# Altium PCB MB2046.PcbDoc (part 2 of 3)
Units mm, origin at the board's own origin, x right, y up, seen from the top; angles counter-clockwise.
Board outline 70 x 82.5 mm, 2 copper layers (Top Layer, Bottom Layer), stack 1.47 mm thick; 179 components, 148 nets, 719 pads, 862 vias.
Unrouted connection lines stored in the file: 135.
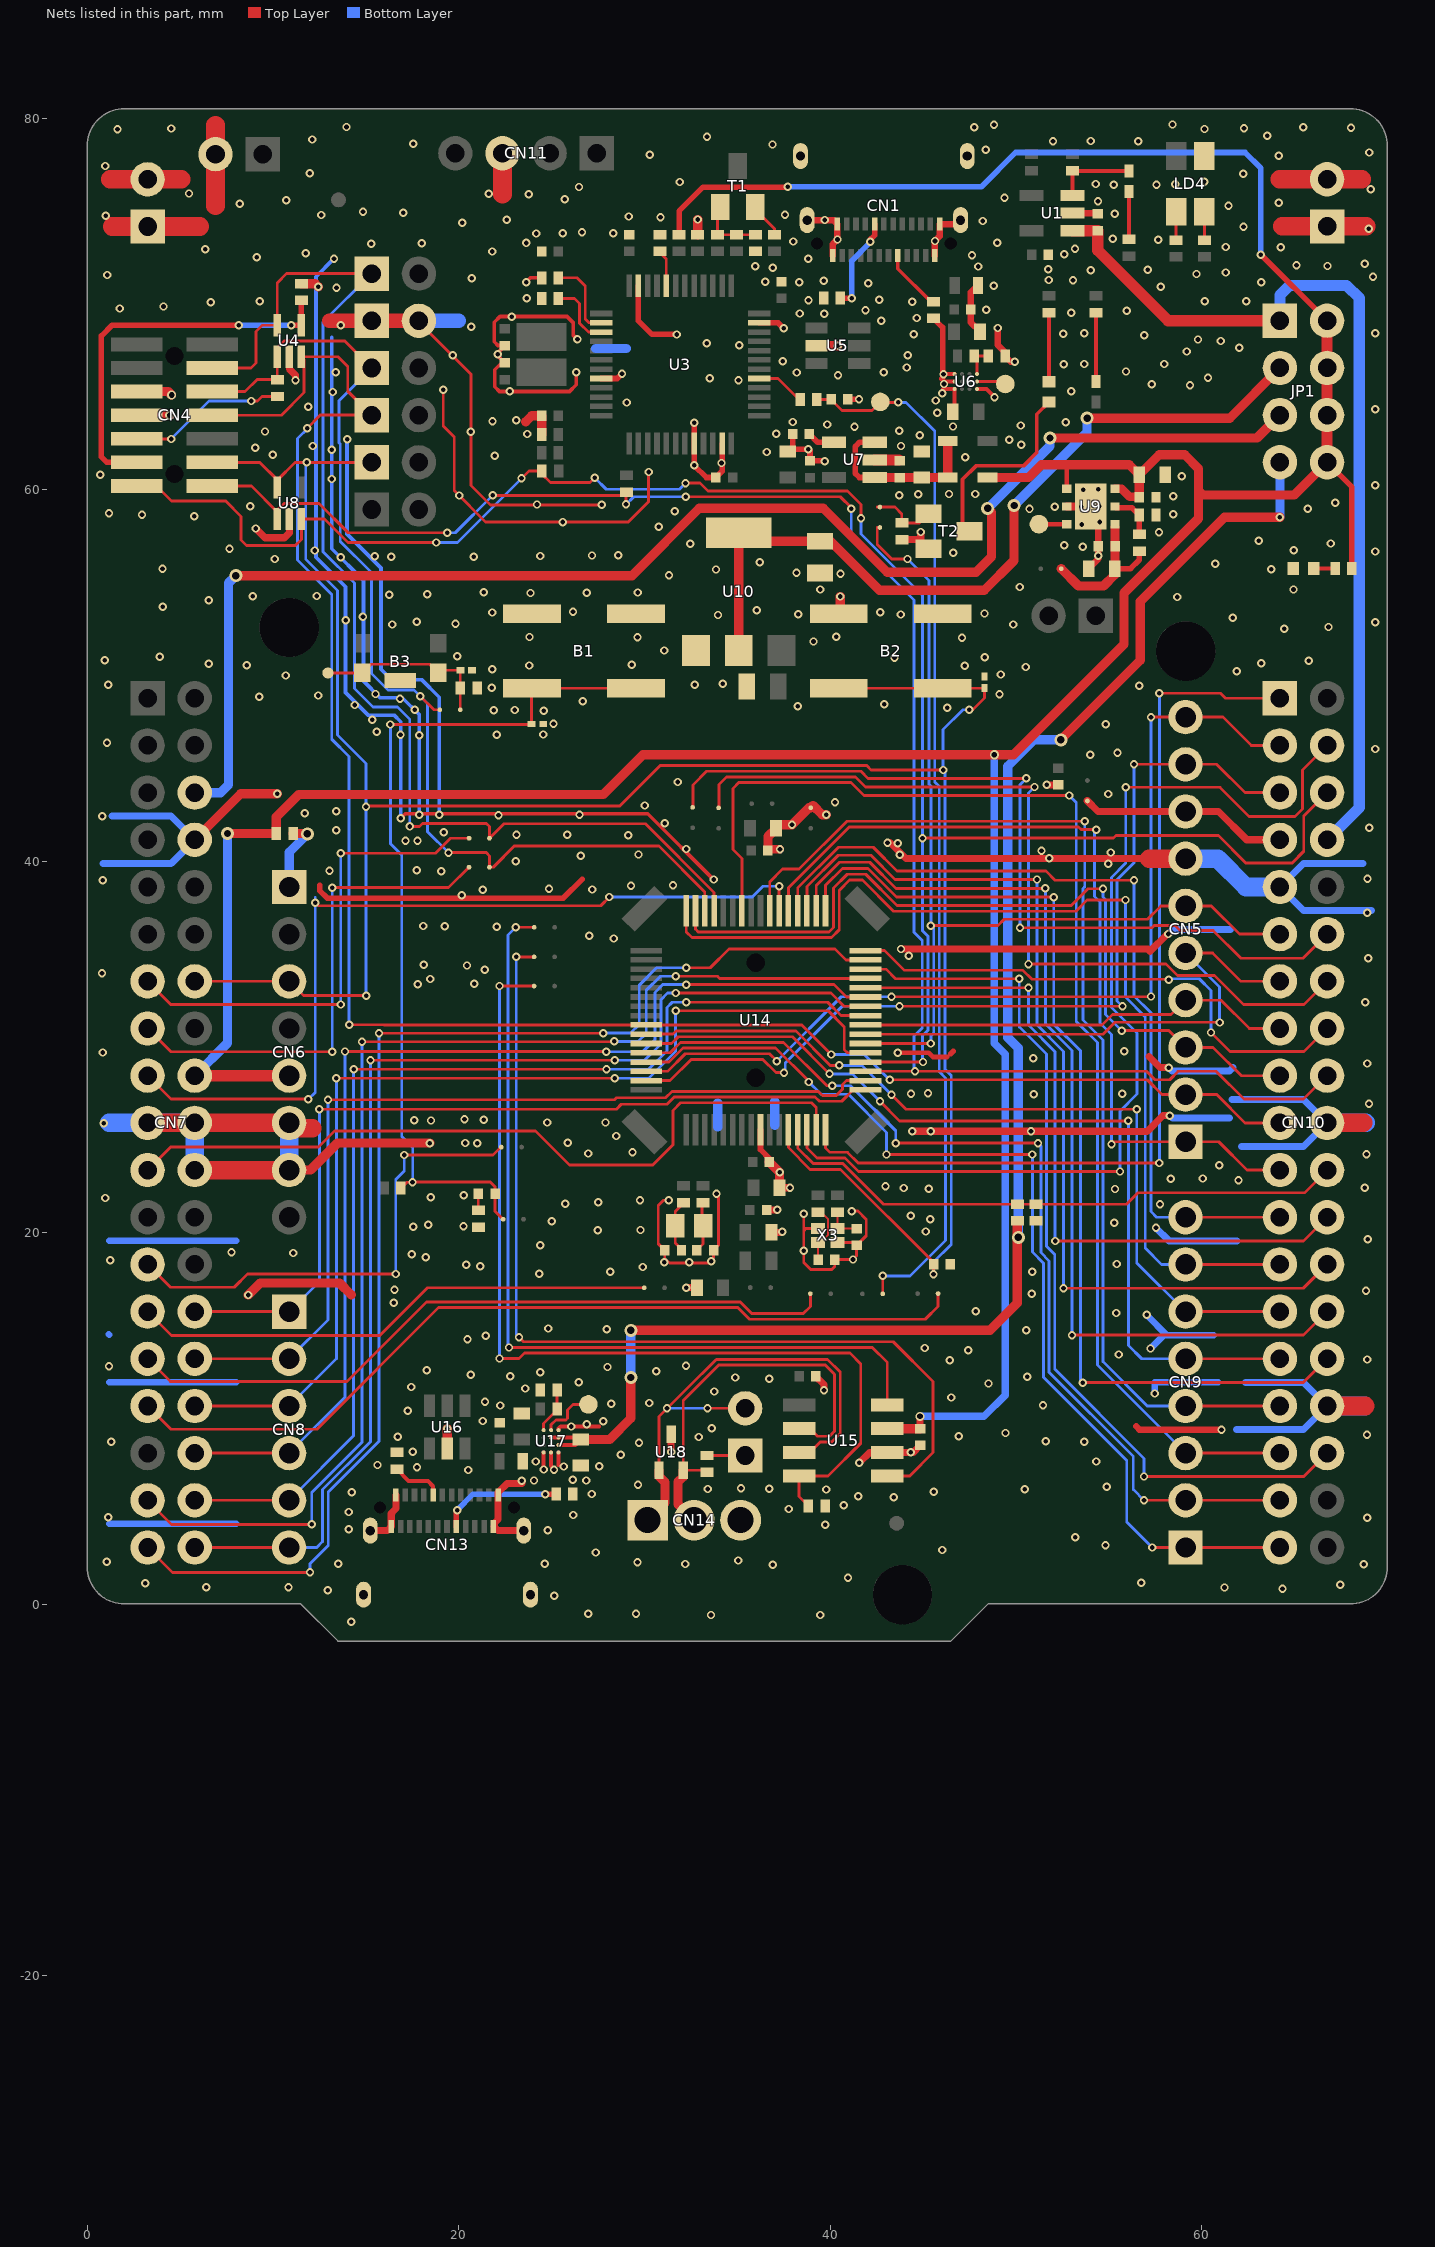
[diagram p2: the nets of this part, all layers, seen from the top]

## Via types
v1: diameter 0.45, hole 0.25, Top Layer to Bottom Layer, tented both sides, 830 vias
v2: diameter 0.7, hole 0.4, Top Layer to Bottom Layer, tented both sides, 21 vias
v3: diameter 0.5, hole 0.3, Top Layer to Bottom Layer, tented both sides, 11 vias

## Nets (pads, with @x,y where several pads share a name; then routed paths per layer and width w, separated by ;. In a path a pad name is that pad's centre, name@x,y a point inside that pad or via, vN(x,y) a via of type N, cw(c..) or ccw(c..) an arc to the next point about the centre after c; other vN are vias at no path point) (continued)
5V: C18.2 C20.2 C41.1 CN6.5 CN7.18 D2.1 JP1.2 JP1.4 JP1.6 JP1.8 R9.2 R31.1 R33.1 U9.1 U9.6 U15.3 | length 208.4
  Top Layer w0.25: U9.1@52.736,60.04 52.736,61.333
  Top Layer w0.3: R9.2@31.863,73.72 31.863,74.993 33.158,76.288 37.7,76.288 v1(37.71,76.298) ; v1(63.18,72.635) 63.18,72.663 JP1.2@66.75,69.093 JP1.2@66.75,69.842 ; JP1.8@66.75,61.473 68.083,60.14 R31.1@68.083,55.753
  Top Layer w0.4: C41.1@44.835,9.45 v3(44.835,10.105)
  Top Layer w0.45: U9.6@55.336,60.04 55.695,60.04 56.118,59.617 56.391,59.617 56.416,59.592 C20.2@56.64,59.592
  Top Layer w0.5: v2(7.552,41.485) R33.1@10.182,41.485 10.182,42.38 11.385,43.583 27.785,43.583 29.923,45.72 49.865,45.72 55.812,51.667 55.812,54.432 59.828,58.448 59.828,59.935 ; U15.3@43.076,9.442 C41.1@44.843,9.442 ; D2.1@48.465,60.65 50.688,60.65 51.38,61.343 56.092,61.343 C18.2@56.64,60.795 C20.2@56.64,59.592 ; C18.2@56.64,60.8 57.71,61.87 59.087,61.87 59.828,61.13 59.828,59.935 ; 59.832,59.712 60.05,59.712 ; JP1.8@66.75,61.473 64.99,59.712 60.05,59.712 ; 59.828,59.935 60.05,59.712
  Top Layer w0.6: CN7.18@5.791,28.448 CN6.5@10.871,28.448 ; C18.2@56.64,60.795 C18.2@56.64,60.8 ; JP1.8@66.75,61.473 JP1.6@66.75,64.013 JP1.4@66.75,66.553 JP1.2@66.75,69.093
  Bottom Layer w0.3: v1(37.71,76.298) 48.132,76.298 49.985,78.15 62.34,78.15 63.18,77.31 v1(63.18,72.635)
  Bottom Layer w0.4: v3(44.835,10.105) 48.28,10.105 49.418,11.243 49.418,29.613 48.84,30.19 v3(48.84,45.722)
  Bottom Layer w0.5: CN7.18@5.791,28.448 7.552,30.209 v2(7.552,41.485)
5V_EXT: CN7.6 JP1.5 | length 78.1
  Top Layer w0.5: v2(8.007,55.37) 29.335,55.37 32.958,58.993 39.632,58.993 43.078,55.547 47.847,55.547 48.683,56.383 48.683,58.78 v2(48.475,58.987) ; v2(51.835,62.777) 62.975,62.777 JP1.5@64.21,64.013
  Bottom Layer w0.5: CN7.6@5.791,43.688 7.183,43.688 7.605,44.11 7.605,54.967 v2(8.007,55.37) ; v2(48.475,58.987) 51.835,62.347 v2(51.835,62.777)
5V_STLK: C1.2 CN10.8 JP1.1 U1.1 | length 49.8
  Top Layer w0.6: U1.1@53.043,73.938 C1.2@54.407,73.938 54.407,72.876 58.19,69.093 JP1.1@64.21,69.093
  Bottom Layer w0.6: JP1.1@64.21,69.093 64.21,70.478 64.73,70.998 67.795,70.998 68.482,70.31 68.482,42.879 CN10.8@66.751,41.148
5V_USB: C42.2 JP1.7 R40.2 U17.A2 U17.A3 U17.B2 | length 87.3
  Top Layer w0.22: U17.B2@24.975,8.966 U17.A2@25.375,8.966 26.473,8.966 C42.2@26.575,8.865 26.276,8.566 U17.A3@25.375,8.566
  Top Layer w0.5: C42.2@26.575,8.865 28.132,8.865 29.268,10 v2(29.268,12.203) ; v2(29.268,14.74) 48.608,14.74 50.074,16.206 R40.2@50.074,20.63 ; v2(52.415,46.527) 56.697,50.81 56.697,53.972 61.232,58.508 v1(64.21,58.508)
  Bottom Layer w0.5: v2(29.268,12.203) v2(29.268,14.74) ; v2(50.125,19.747) 50.125,29.935 49.555,30.505 49.555,45.1 50.982,46.527 v2(52.415,46.527) ; v1@64.21,58.528 JP1.7@64.21,61.473
5V_VIN: C22.2 JP1.3 U10.2 U10.4 | length 44.2
  Top Layer w0.5: U10.2@35.077,51.047 35.077,57.397 U10.4@35.365,57.397 ; U10.4@35.077,57.685 U10.4@35.365,57.397 ; v2(49.897,59.145) 49.897,56.188 48.292,54.582 42.653,54.582 40.02,57.215 C22.2@39.45,57.215 35.547,57.215 U10.4@35.365,57.397 ; v2(53.83,63.847) 61.505,63.847 JP1.3@64.21,66.553
  Bottom Layer w0.5: v2(49.897,59.145) 53.83,63.077 v2(53.83,63.847)
CAN_N: CN14.2 R46.1 U15.6 U18.2 | length 22.6
  Top Layer w0.152: 32.087,9.842 U18.2@32.087,7.204 33.265,7.204 R46.1@33.368,7.101 ; U15.6@38.326,9.442 38.91,9.442 39.317,9.036 39.96,9.036 40.233,9.309 40.233,9.96
  Top Layer w0.155: 32.087,9.842 32.087,10.955 34,12.868 39.737,12.868 40.233,12.372 40.233,9.96
  Top Layer w0.5: U18.2@32.087,7.204 32.087,6.862 31.81,6.585 31.81,5.383 CN14.2@32.675,4.518
CAN_P: CN14.1 JP9.2 U15.7 U18.1 | length 27.6
  Top Layer w0.152: U18.1@30.787,7.204 30.787,10.092 32.271,11.576 ; v1(33.393,10.545) 33.397,10.541 JP9.2@35.425,10.541 ; U15.7@38.326,8.172 38.905,8.172 39.464,8.731 40.086,8.731 40.539,9.184 40.539,12.498 39.862,13.175
  Top Layer w0.155: 32.271,11.576 33.87,13.175 39.862,13.175
  Top Layer w0.5: CN14.1@30.175,4.518 31.11,5.453 31.11,6.568 30.787,6.89 U18.1@30.787,7.204
  Bottom Layer w0.152: v1(31.213,10.545) v1(33.393,10.545)
FDCAN_RX: SB11.2 U15.4 | length 46.8
  Top Layer w0.152: v1(22.705,13.815) 22.71,13.82 42.267,13.82 43.076,13.012 U15.4@43.076,10.712 ; v1(23.065,36.433) 23.069,36.436 SB11.2@24.063,36.436
  Bottom Layer w0.152: v1(22.705,13.815) 22.649,13.871 22.649,36.017 v1(23.065,36.433)
FDCAN_STBY: R48.1 SB13.2 U15.8 | length 51.9
  Top Layer w0.152: v1(22.194,13.223) 23.255,13.223 23.548,13.516 41.062,13.516 41.645,12.933 41.645,8.657 39.89,6.902 U15.8@38.326,6.902 38.326,5.794 R48.1@38.825,5.295 ; v1@22.194,33.274 SB13.2@24.063,33.274
  Bottom Layer w0.152: v1(22.194,13.223) v1(22.194,33.279)
FDCAN_TX: SB12.2 U15.1 | length 51.6
  Top Layer w0.152: v1(23.102,34.845) v1(23.102,34.845) SB12.2@24.063,34.846 ; v1(23.245,14.37) 23.491,14.124 43.396,14.124 45.54,11.98 45.54,8.157 44.285,6.902 U15.1@43.076,6.902
  Bottom Layer w0.152: v1(23.102,34.845) 23.102,14.513 v1(23.245,14.37)
GND: B1.1 B1.2 B2.1 B2.2 B3.5 C1.1 C2.2 C3.2 C4.1 C5.2 C6.2 C7.2 C8.1 C9.2 C10.1 C11.1 C12.1 C13.1 C14.1 C15.1 C16.1 C17.1 C18.1 C19.2 C20.1 C21.1 C22.1 C23.1 C24.1 C25.2 C26.1 C27.1 C28.1 C30.1 C31.2 C32.1 C33.1 C34.1 C35.1 C36.1 C37.2 C38.2 C39.2 C40.2 C41.2 C42.1 C43.1 CN1.A1 CN1.A12 CN1.B1 CN1.B12 CN1.SH1 CN1.SH2 CN1.SH3 CN1.SH4 CN2.1 CN2.2 CN3.1 CN3.2 CN4.5 CN4.7 CN5.7 CN6.6 CN6.7 CN7.8 CN7.19 CN7.20 CN7.22 CN10.9 CN10.20 CN10.32 CN11.3 CN12.1 CN12.2 CN13.A1 CN13.A12 CN13.B1 CN13.B12 CN13.SH1 CN13.SH2 CN13.SH3 CN13.SH4 CN14.3 JP3.2 LD3.2 LD4.3 R3.1 R5.2 R8.1 R13.2 R14.1 R17.2 R18.2 R19.2 R21.1 R24.2 R28.1 R29.2 R32.1 R39.1 R41.2 R43.1 R45.2 R47.2 R48.2 SB8.2 T2.2 U1.2 U2.2 U3.8 U3.20 U3.23 U3.35 U3.47 U4.2 U5.2 U6.A1 U6.A4 U6.B4 U6.C4 U7.2 U8.2 U9.2 U9.EP U10.1 U11.2 U12.2 U13.2 U14.9 U15.2 U16.2 U17.A1 U17.A4 U17.B4 U17.C4 U18.3 U19.2 X3.2 X3.4 | length 516.7
  Top Layer w0.152: CN12.2@17.856,69.088 17.856,69.008 20.655,66.21 20.655,60.219 21.71,59.164 v1@27.702,59.164 ; v1(19.166,65.37) 19.166,63.431 19.76,62.837 19.76,59.942 21.45,58.252 v1(25.598,58.252) 29.128,58.252 30.225,59.35 v1(30.225,60.948) ; v1(31.305,21.745) 31.02,21.745 30.742,21.467 30.742,19.402 C33.1@31.095,19.05 31.095,18.613 31.345,18.363 33.44,18.363 33.724,18.646 C34.1@33.724,19.05 33.988,19.314 33.988,21.828 ; v1@33.873,21.943 33.988,21.828 ; v1(33.883,22.1) 33.988,21.995 33.988,21.828 ; v1(38.575,21.02) 38.575,20.092 ; 38.587,20.22 38.703,20.22 ; X3.4@39.35,20.22 38.703,20.22 ; X3.2@40.4,19.47 41.274,19.47 C32.1@41.424,19.32 ; v1(41.17,21.157) 41.495,21.157 41.938,20.715 41.938,19.834 C32.1@41.424,19.32 ; 38.575,20.092 38.575,18.398 38.95,18.022 40.08,18.022 40.25,18.192 C35.1@40.25,18.55 v1(41.225,18.55) 41.424,18.749 C32.1@41.424,19.32 ; 38.575,20.092 38.703,20.22
  Top Layer w0.2: v1(16.877,42.305) 17.127,42.554 30.176,42.554 v1(33.723,39.007) ; C8.1@22.477,67.756 22.117,67.756 21.917,67.955 21.917,69.007 22.23,69.32 25.832,69.32 26.16,68.992 26.16,68.325 v1(26.392,68.093) ; C8.1@22.48,67.707 22.477,67.707 22.432,67.707 22.057,67.333 22.057,67.247 C9.2@22.477,66.827 22.314,66.827 21.937,66.45 21.937,65.54 22.193,65.285 25.97,65.285 26.333,65.648 v1(26.333,66.322) ; v1(23.633,71.165) 23.871,71.403 R13.2@24.471,71.403
  Top Layer w0.22: v1@24.575,7.43 U17.C4@24.575,8.166 ; 24.975,7.448 U17.B4@24.975,8.166 ; 25.375,7.487 U17.A4@25.375,8.166 ; U17.A1@25.375,9.366 25.375,9.449 25.493,9.567 27.56,9.567 ; 46.065,65.418 U6.A4@46.701,65.418 46.701,64.299 C11.1@46.596,64.195 ; v1@46.093,65.818 U6.B4@46.701,65.818 ; v1(46.097,66.218) U6.C4@46.701,66.218 ; U6.A1@47.901,65.418 48.407,65.418 v1(48.847,64.978)
  Top Layer w0.254: v1(43.63,29.687) 45.202,29.687 45.212,29.678 45.307,29.678 45.525,29.46 46.285,29.46
  Top Layer w0.3: 12.518,38.7 12.518,38.413 12.923,38.008 25.63,38.008 26.642,39.02 ; C8.1@22.477,67.707 C8.1@22.477,67.756 ; U3.8@27.678,65.982 28.535,65.982 v1(28.795,66.242) ; U3.47@29.678,70.982 29.678,69.087 30.412,68.352 v1(31.745,68.352) ; v1(32.683,63.608) 32.678,63.603 U3.20@32.678,62.482 v1(32.678,61.305) 33.332,60.65 C19.2@33.842,60.65 34.178,60.986 U3.23@34.178,62.482 ; U3.35@36.178,68.982 37.2,68.982 v1(37.495,68.688) ; U14.9@36.249,25.533 36.249,24.464 36.721,23.992 C27.1@36.721,23.8 ; C14.1@37.71,62.05 C14.1@37.837,62.178 ; C13.1@37.979,62.994 37.979,62.319 C14.1@37.837,62.178 ; v1@39.687,61.55 C16.1@38.911,61.55 38.911,62.094 v1(38.827,62.178) C14.1@37.837,62.178 ; C10.1@40.946,64.858 41.547,64.858 v1(41.55,64.855) ; R19.2@45.564,69.222 46.049,68.737 46.049,67.205 46.055,67.199 46.055,66.008 46.012,65.965 ; 46.495,29.633 46.63,29.767
  Top Layer w0.35: CN1.SH2@38.76,74.508 40.18,74.508 CN1.B1@40.39,74.298 v1(40.39,73.468) 40.14,73.218 CN1.A12@40.14,72.598 ; CN1.A1@45.64,72.598 v1(45.64,73.383) 45.89,73.633 CN1.B12@45.89,74.298 46.81,74.298 CN1.SH1@47.02,74.508 ; U2.2@47.951,70.992 47.571,70.612 C6.2@47.571,69.698 47.571,68.998 C7.2@48.071,68.498 ; v1(49.013,68.7) 49.013,67.795 49.417,67.391 R21.1@49.417,67.188 49.722,66.883 v1(49.927,66.883) ; U1.2@53.043,74.888 C1.1@54.357,74.888 ; C23.1@53.917,55.748 54.435,56.266 C21.1@54.435,56.947 54.435,58.178 v1(54.512,58.255) ; 56.47,9.577 56.632,9.416 ; 56.632,9.396 v1(61.067,9.396)
  Top Layer w0.38: CN13.SH1@15.241,3.958 16.161,3.958 CN13.B12@16.371,4.168 16.371,4.864 16.439,4.932 16.439,4.961 16.621,5.144 CN13.A1@16.621,5.868 ; CN13.B1@21.907,4.168 22.117,3.958 CN13.SH2@23.501,3.958 ; CN13.B1@21.923,4.168 21.923,4.36 22.121,4.559 CN13.A12@22.121,5.868 22.121,6.009 22.615,6.502 v1@23.405,6.502 ; U18.3@31.437,9.154 31.437,8.19 v1(31.44,8.187) ; v1(32.247,17.04) 32.25,17.043 C37.2@32.825,17.043 ; C30.1@36.58,21.216 v1@37.149,21.216 ; C31.2@36.83,20.016 v1@37.383,20.016 ; C28.1@37.276,22.416 v1@37.84,22.416 ; C38.2@39.226,12.258 39.665,11.819 v1(39.665,11.505) ; v1(41.573,7.615) 42.13,8.172 U15.2@43.076,8.172 44.473,8.172 C41.2@44.843,8.542 ; v1(43.085,40.995) 43.228,40.995 44.091,40.132 57.18,40.132 ; v1(43.813,35.272) 57.095,35.272 57.22,35.147 58.15,36.077 v1(58.2,36.077) ; R29.2@43.855,57.31 44.795,57.31 T2.2@45.295,56.81 44.875,57.23 v1(44.875,57.717) ; v1(44.409,25.459) 55.408,25.459 55.417,25.45 57.065,25.45 57.915,26.3 v1(58.285,26.3) ; 57.158,29.472 57.747,28.883 v1(58.218,28.883)
  Top Layer w0.381: v1(9.078,57.905) 9.574,57.409 10.621,57.409 10.882,57.669 U8.2@10.882,58.415 ; U4.2@10.882,67.153 10.882,66.488 11.215,66.155 v1(11.215,65.882) ; v1(51.65,44.105) C25.2@52.28,44.105
  Top Layer w0.45: C26.1@36.65,40.57 36.727,40.648 v1(37.297,40.648) ; U9.2@52.736,59.09 U9.EP@54.036,59.09
  Top Layer w0.5: CN4.7@2.672,64.007 v3(4.453,64.007) ; CN4.5@2.672,65.277 4.363,65.277 v3(4.545,65.095) ; CN7.8@5.791,41.148 8.266,43.623 v1(10.24,43.623) ; v1(8.665,16.645) 9.312,17.292 13.578,17.292 14.21,16.66 ; CN6.7@10.871,23.368 12.023,23.368 13.475,24.82 v1(18.435,24.82) ; R14.1@11.532,71.087 12.275,71.087 v1(12.445,70.918) ; U16.2@19.387,8.382 v1(19.387,9.447) v1(19.387,9.447) ; 23.615,63.66 23.927,63.972 C12.1@24.471,63.972 R24.2@24.471,62.972 ; R5.2@32.863,73.721 v1@32.863,74.537 ; C26.1@36.65,40.57 36.65,41.331 C43.1@37.09,41.77 37.28,41.96 v1(37.945,41.96) 38.855,42.87 SB8.2@38.955,42.87 39.075,42.99 39.573,42.493 v1(39.785,42.493) ; C27.1@36.721,23.8 v1(37.276,23.245) C28.1@37.276,22.416 ; U5.2@39.261,67.742 v1(40.411,67.742) ; B2.1@40.456,53.308 40.545,53.397 v1(40.545,54.243)
  Top Layer w0.6: U7.2@42.399,61.6 C17.1@43.688,61.6
  Top Layer w0.8: 13.029,69.088 CN12.1@15.316,69.088 CN12.2@17.856,69.088
  Top Layer w1: 1.245,76.703 CN3.2@3.255,76.703 5.068,76.703 ; 1.352,74.163 CN3.1@3.255,74.163 6.065,74.163 ; CN7.19@3.251,25.908 CN6.6@10.871,25.908 11.149,25.63 12.117,25.63 ; CN7.22@5.791,23.368 CN6.7@10.871,23.368 ; 6.91,75.29 JP3.2@6.91,78.058 6.91,79.606 ; 22.36,75.91 CN11.3@22.36,78.108 ; 57.18,40.132 CN5.7@59.131,40.132 ; 64.209,76.708 CN2.2@66.751,76.708 68.623,76.708 ; 64.333,74.168 CN2.1@66.751,74.168 v1@68.852,74.168 ; CN10.32@66.751,10.668 68.815,10.668 ; CN10.20@66.751,25.908 68.687,25.908
  Bottom Layer w0.2: 13.163,68.198 13.163,56.82 14.87,55.113 14.87,49.695 15.767,48.797 16.968,48.797 17.875,47.89 v1(17.875,42.503) ; v1(13.29,72.435) 12.317,71.463 12.317,56.355 13.902,54.77 13.902,49.075 15.118,47.86 16.52,47.86 16.877,47.503 v1(16.877,42.305) ; v1@13.985,62.613 13.985,57.615 15.817,55.782 15.817,50.33 16.377,49.77 18.003,49.77 18.95,48.823 v1(18.95,42.503)
  Bottom Layer w0.35: 1.15,14.53 1.184,14.496 ; 1.184,4.316 8.021,4.316 ; 1.184,11.936 8.021,11.936 ; 1.184,19.556 8.021,19.556 ; v1(57.035,15.57) 58.137,14.467 ; v1(57.242,13.76) 57.95,14.467 58.137,14.467 ; v1(57.48,11.342) 57.48,11.94 60.875,11.94 60.882,11.947 ; 60.655,14.467 58.137,14.467
  Bottom Layer w0.38: v1(57.543,20.255) 58.237,19.561 61.886,19.561 ; v1(58.2,36.077) 58.442,36.319 61.557,36.319 ; v1(58.218,28.883) 58.395,28.705 61.502,28.705 61.695,28.898 ; v1(58.285,26.3) 58.42,26.165 61.488,26.165 ; 61.625,27.17 63.681,27.17 63.686,27.175 65.484,27.175 CN10.20@66.751,25.908 65.479,24.635 63.686,24.635 63.683,24.633 62.132,24.633 ; 61.887,9.413 61.899,9.401 65.484,9.401 CN10.32@66.751,10.668 65.479,11.941 62.353,11.941 ; 68.682,39.875 65.479,39.875 CN10.9@64.211,38.608 65.484,37.335 69.152,37.335
  Bottom Layer w0.381: 0.85,39.88 4.523,39.88 CN7.8@5.791,41.148 4.519,42.42 1.342,42.42
  Bottom Layer w0.5: 27.385,67.595 29.025,67.595 ; 33.953,25.682 33.953,26.981 ; 37.018,25.787 37.018,27.055
  Bottom Layer w0.8: CN12.2@17.856,69.088 20.001,69.088
  Bottom Layer w1: 1.18,25.908 CN7.19@3.251,25.908 CN7.20@5.791,25.908 CN7.22@5.791,23.368 ; CN6.7@10.871,23.368 CN6.6@10.871,25.908 ; CN5.7@59.131,40.132 60.86,40.132 62.385,38.608 CN10.9@64.211,38.608 ; CN10.32@66.751,10.668 68.78,10.668 ; CN10.20@66.751,25.908 68.832,25.908
  other v1: 14.212,-0.95 33.583,-0.583 39.47,-0.583 26.98,-0.525 29.547,-0.525 25.15,0.445 12.952,0.743 64.353,0.82 10.835,0.903 61.23,0.893 6.402,0.915 67.46,1.035 3.12,1.125 56.743,1.145 40.957,1.425 36.902,2.12 68.715,2.147 24.643,2.173 32.193,2.16 13.523,2.183 29.625,2.255 1.048,2.285 35.05,2.352 27.385,2.778 46.035,2.917 54.82,3.163 53.19,3.6 24.79,3.978 14.085,4.032 39.727,4.28 68.915,4.643 1.13,4.683 26.175,4.795 14.08,4.962 37.763,5.12 40.732,5.318 43.425,5.747 41.515,5.803 27.155,5.933 14.24,6.023 45.582,6.048 39.787,6.172 50.467,6.18 33.413,6.2 36.715,6.212 35.195,6.248 54.89,6.32 29.653,6.43 23.395,6.645 24.052,6.655 26.865,6.655 26.135,6.687 20.51,7.217 24.58,7.25 25.128,7.24 17.758,7.368 25.648,7.41 27.567,7.42 15.627,7.49 24.15,7.678 54.33,7.678 28.725,8.05 44.33,8.18 17.52,8.205 29.707,8.68 1.295,8.74 53.67,8.74 51.607,8.762 32.915,9 16.712,9.018 46.915,9.045 68.9,9.118 49.44,9.213 33.615,9.473 26.057,9.565 26.888,9.687 27.78,9.845 21.3,9.86 17.257,10.42 22.237,10.69 51.46,10.697 28.218,10.785 30.262,10.827 21.415,10.9 46.523,11.125 33.755,11.445 23.59,11.605 17.443,11.688 48.522,11.875 26.472,11.953 36.722,12.125 34.89,12.203 50.612,12.24 22.778,12.273 20.647,12.353 24.39,12.49 30.64,12.54 18.277,12.592 28.015,12.762 1.175,12.812 32.235,12.828 46.443,13.123 68.915,13.167 55.54,13.437 47.427,13.67 45.09,13.792 20.475,14.265 21.46,14.447 50.548,14.75 27.978,14.805 24.827,14.837 55.397,15.675 47.835,15.767 16.508,16.22 50.858,16.702 68.842,16.873 16.542,16.917 24.33,17.795 28.168,17.89 50.885,17.89 29.903,18.147 21.155,18.19 20.402,18.265 55.423,18.313 31.07,18.397 32.417,18.41 33.6,18.467 1.25,18.52 18.22,18.667 17.482,18.832 11.093,18.902 7.77,18.935 38.575,19.018 24.392,19.328 68.943,19.637 37.41,20.042 45.145,20.058 27.48,20.122 29.787,20.145 17.552,20.31 20.258,20.345 18.36,20.43 55.293,20.532 25.007,20.605 45.38,20.717 44.34,20.9 37.155,21.223 25.74,21.548 57.757,21.532 27.517,21.632 29.76,21.75 0.978,21.868 18.487,21.895 20.275,22.015 45.305,22.36 55.333,22.347 37.84,22.407 43.96,22.405 68.772,22.417 42.978,22.497 61.978,22.818 58.335,22.9 60.057,22.918 60.942,23.625 68.872,24.228 26.978,24.26 29.36,24.332 20.36,24.825 20.993,24.82 25.87,24.843 28.475,25.205 45.422,25.458 50.81,25.46 0.887,25.88 24.775,25.93 27.902,25.93 18.51,26.035 17.608,26.055 21.34,26.075 20.315,26.105 69.005,26.942 44.352,27.47 50.96,27.453 55.72,27.47 45.267,27.495 68.91,29.108 50.932,29.39 0.843,29.695 55.83,29.773 68.802,32.41 17.8,33.38 20.837,33.405 18.463,33.655 0.795,33.965 21.398,34.152 20.45,34.38 18.125,34.412 68.973,34.777 44.225,34.91 28.355,35.832 27.035,35.985 22.04,36.467 18.085,36.505 19.25,36.5 68.91,37.223 20.158,38.168 21.305,38.465 27.19,38.47 24.86,38.513 29.275,38.68 31.535,38.703 0.843,38.963 68.925,39.045 19.058,39.452 13.047,39.48 17.75,39.502 54.96,39.855 23.072,40 51.8,40.157 26.575,40.297 43.743,40.35 29.683,40.352 55.113,40.462 51.377,40.568 32.243,40.655 43.643,40.96 17.135,41.103 17.782,41.103 25.843,41.41 29.135,41.395 23.112,41.42 19.19,41.555 13.407,41.66 69.02,41.8 31.095,42.038 0.813,42.413 22.143,42.473 26.505,42.487 11.712,42.585 13.407,42.687 30.017,42.998 40.257,43.178 54.977,43.61 31.798,44.262 54.003,45.73 55.47,45.832 69.335,46.038 1.068,46.365 17.868,46.782 22.045,46.802 16.87,46.812 24.557,46.818 15.595,46.965 54.832,47.367 25.108,47.397 15.348,47.603 21.89,48.115 24.58,48.1 23.022,48.132 17.638,48.15 46.31,48.26 38.258,48.345 14.4,48.405 42.918,48.448 26.688,48.597 16.84,48.737 9.273,48.845 12.432,48.915 15.525,48.995 49.113,48.993 21.78,49.325 56.647,49.442 1.13,49.5 32.703,49.498 34.225,49.54 10.697,49.993 49.183,50.05 61.895,50.223 21.798,50.335 50.53,50.45 23.8,50.532 47.248,50.525 8.595,50.552 29.325,50.572 6.545,50.628 63.215,50.655 65.768,50.79 0.94,50.822 43.462,50.952 48.322,50.978 3.9,51.005 19.915,51.03 31.075,51.337 39.1,51.82 47.095,52.018 29.63,52.05 23.812,52.065 40.318,52.088 64.435,52.515 66.827,52.603 16.425,52.737 49.85,52.735 19.83,52.783 69.335,52.85 17.745,52.887 13.928,52.963 61.673,53.108 14.845,53.15 33.96,53.25 43.797,53.275 38.278,53.298 48.308,53.328 21.802,53.382 42.703,53.398 26.155,53.422 36.047,53.502 4.065,53.687 6.55,54.035 58.678,54.217 8.91,54.255 12.355,54.27 16.268,54.332 18.31,54.368 23.865,54.435 21.352,54.472 26.902,54.452 29.643,54.46 39.46,54.62 64.94,54.622 50.21,54.758 31.32,55.395 40.558,55.465 38.185,55.53 33.85,55.7 4.052,55.74 63.745,55.72 60.738,56.018 36.21,56.082 10.09,56.263 13.647,56.36 16.362,56.39 20.817,56.393 15.48,56.413 24.398,56.427 27.177,56.45 54.422,56.43 28.595,56.46 46.62,56.6 69.335,56.667 12.245,56.723 64.965,56.745 7.66,56.807 53.588,56.925 52.603,57.012 32.46,57.082 66.95,57.102 63.067,57.238 57.703,57.7 30.78,57.997 53.542,58.122 5.773,58.568 2.955,58.642 58.462,58.678 1.175,58.735 31.625,58.843 50.73,58.96 65.718,58.963 52.09,59.077 53.51,59.077 8.788,59.103 54.48,59.1 24.215,59.195 27.702,59.183 67.185,59.295 58.47,59.648 20.022,59.68 43.717,59.698 44.742,59.755 46.397,59.762 47.81,59.76 53.62,59.993 54.425,60.015 69.335,60.235 13.157,60.57 58.923,60.71 0.707,60.802 34.145,61.433 39.71,61.527 47.28,61.743 21.947,61.817 9.985,61.875 36.575,62.028 13.157,62.145 9.048,62.245 12.14,62.348 43.81,62.348 50.287,62.42 49.64,62.685 14.006,62.708 44.813,62.925 23.685,62.993 37.105,63 9.575,63.13 20.655,63.123 43.717,63.173 41.31,63.382 46.615,63.395 50.267,63.455 39.847,63.508 37.982,63.638 52.69,63.635 21.82,63.682 23.105,63.735 45.768,64.13 69.335,64.327 11.903,64.462 29.05,64.69 45.688,64.798 46.035,65.18 13.22,65.253 22.742,65.29 52.983,65.303 59.372,65.61 57.312,65.67 46.127,65.683 35.067,65.88 33.523,66 60.343,66.02 40.42,66.165 38.2,66.302 13.375,66.32 42.875,66.322 55.925,66.36 44.128,66.575 52.58,66.74 53.675,66.765 57.99,66.765 37.453,66.913 19.675,67.235 44.178,67.242 22.095,67.295 59.2,67.435 62.018,67.64 35.107,67.767 33.35,67.885 61.035,68.003 59.802,68.077 56.91,68.305 44.5,68.358 52.545,68.4 53.683,68.418 69.335,68.418 20.677,68.775 13.647,68.848 42.755,69.097 44.66,69.235 22.858,69.297 38.362,69.48 39.68,69.467 52.983,69.513 55.97,69.62 41.898,69.665 48.398,69.675 1.755,69.752 4.11,69.858 6.66,70.09 44.415,70.112 9.283,70.145 60.163,70.138 62.405,70.138 38.83,70.187 42.643,70.217 23.66,70.297 13.42,70.872 57.787,70.928 48.807,70.97 42.048,71.118 38.338,71.16 63.202,71.168 36.512,71.19 39.648,71.242 51.76,71.288 53.075,71.268 20.703,71.378 69.22,71.45 1.078,71.553 59.718,71.607 61.3,71.69 54.035,71.807 57.105,71.835 51.745,71.865 36.908,71.945 35.957,72.023 47.975,72.01 66.775,72.037 65.105,72.088 68.772,72.168 38.825,72.432 9.12,72.518 47.633,72.608 52.6,72.662 11.76,72.73 21.805,72.815 6.355,72.945 53.18,72.963 61.293,73.06 64.247,73.05 15.285,73.24 18.005,73.257 23.64,73.28 49,73.287 38.012,73.358 57.66,73.445 55.213,73.502 24.172,73.79 25.598,73.798 28.325,73.798 26.64,73.852 68.985,74.035 62.248,74.143 20.182,74.357 48.212,74.457 22.592,74.53 39.703,74.517 32.868,74.545 30.865,74.66 29.158,74.7 1.005,74.745 12.61,74.78 37.565,74.802 55.31,74.858 17.007,74.905 14.847,74.96 61.445,75.277 8.21,75.387 64.157,75.447 54.42,75.515 10.707,75.585 25.71,75.625 49.385,75.715 23.777,75.892 21.618,75.925 5.483,75.94 69.1,76.165 26.478,76.288 55.257,76.41 57.565,76.405 58.578,76.44 54.3,76.452 31.9,76.557 60.143,76.58 62.238,77 11.975,77.03 0.97,77.422 64.14,77.983 30.292,78.035 69.017,78.145 48.375,78.303 36.895,78.58 17.555,78.618 51.995,78.752 56.575,78.745 54.025,78.768 12.117,78.848 33.367,78.995 63.528,79.055 1.63,79.4 60.147,79.415 4.52,79.437 62.275,79.46 68.035,79.487 47.75,79.513 65.465,79.505 13.958,79.52 48.815,79.64 58.425,79.657
GNDDetect: CN4.11 R14.2 U4.4 | length 20.9
  Top Layer w0.3: CN4.11@2.672,61.467 1.061,61.467 0.767,61.76 0.767,68.275 1.342,68.85 v1(8.16,68.85) ; v1(10.983,68.85) 10.986,68.853 U4.4@11.532,68.853 R14.2@11.532,70.187
  Bottom Layer w0.3: v1(8.16,68.85) v1(10.983,68.85)
MCU.MCO: C10.2 R23.2 SB20.1 TP2.1 | length 56.4
  Top Layer w0.152: R23.2@39.277,64.858 C10.2@40.046,64.858 40.636,64.267 42.245,64.267 TP2.1@42.697,64.719 42.722,64.695 v1(43.663,64.695) ; SB20.1@42.83,16.705 42.83,17.667 v1(42.835,17.672)
  Bottom Layer w0.152: v1(42.835,17.672) 44.305,17.672 46.216,19.584 46.216,28.321 45.876,28.662 45.876,44.019 45.627,44.268 45.627,63.153 44.085,64.695 v1(43.663,64.695)
NetB1_3: B1.3 B1.4 C29.2 R34.1 SB15.1 U13.1 | length 47.5
  Top Layer w0.152: v1(16.322,47.353) 23.905,47.353 U13.1@23.925,47.373 B1.3@23.925,49.287 ; R34.1@16.89,22.393 17.209,22.712 v1(17.513,22.712) ; v1@17.515,22.728 21.698,22.728 21.958,22.467 C29.2@21.958,22.1 21.958,21.152 SB15.1@22.39,20.72 ; B1.3@23.946,49.308 B1.4@29.546,49.308
  Bottom Layer w0.152: v1(16.322,47.353) 16.328,47.347 16.328,40.932 16.937,40.322 16.937,25.18 17.526,24.591 v1@17.526,22.712
NetB3_1: B3.1 B3.3 R32.2 SB3.2 TP4.1 U11.1 | length 9.7
  Top Layer w0.152: TP4.1@12.96,50.13 12.963,50.133 B3.1@14.805,50.133 15.272,50.6 18.438,50.6 B3.3@18.905,50.133 19.045,50.273 U11.1@20.088,50.273 R32.2@20.088,49.322 SB3.2@20.088,48.145
NetC13_2: C13.2 U7.4 | length 1.5
  Top Layer w0.3: C13.2@38.879,62.994 39.323,62.55 U7.4@40.199,62.55
NetC15_2: C15.2 C17.2 D1.2 D2.2 U7.1 U7.3 | length 9.6
  Top Layer w0.3: U7.1@42.399,60.65 41.57,60.65 41.353,60.867 41.353,62.323 41.58,62.55 U7.3@42.399,62.55
  Top Layer w0.5: U7.1@42.399,60.65 C17.2@43.738,60.65 C15.2@44.937,60.65 D2.2@46.325,60.65 D1.2@46.325,62.611
NetC21_2: C21.2 C23.2 R30.2 SB2.1 U9.4 | length 8
  Top Layer w0.3: C23.2@55.318,55.748 56.168,55.748 56.64,56.22 R30.2@56.64,56.685
  Top Layer w0.5: SB2.1@52.435,55.738 53.365,54.808 54.713,54.808 55.318,55.413 C23.2@55.318,55.748 ; C23.2@55.336,55.766 U9.4@55.336,57.97
NetC29_1: C29.1 R41.1 | length 0.9
  Top Layer w0.152: R41.1@21.057,21.2 C29.1@21.057,22.1
NetC32_2: C32.2 R38.1 X3.3 | length 2
  Top Layer w0.1: R38.1@40.4,21.192 X3.3@40.4,20.22 C32.2@41.424,20.22
NetC33_2: C33.2 R35.1 X2.2 | length 2.9
  Top Layer w0.152: C33.2@32.055,19.05 31.66,19.444 X2.2@31.66,20.369 31.66,21.132 R35.1@32.142,21.614
NetC34_2: C34.2 R36.1 X2.1 | length 2.6
  Top Layer w0.152: C34.2@32.824,19.05 33.16,19.386 X2.1@33.16,20.369 ; X2.1@33.1,20.369 R36.1@33.1,21.526
NetC35_2: C35.2 R37.1 X3.1 | length 3.2
  Top Layer w0.1: C35.2@39.35,18.55 X3.1@39.35,19.47 39.487,19.47 39.875,19.858 39.875,20.735 39.508,21.102 R37.1@39.35,21.102
NetCN1_A5: CN1.A5 R19.1 | length 3.4
  Top Layer w0.2: CN1.A5@43.64,72.598 43.64,71.894 45.412,70.122 R19.1@45.564,70.122
NetCN1_B5: CN1.B5 R17.1 | length 5.1
  Top Layer w0.3: R17.1@40.548,70.303 v1(41.16,70.303) ; v1@42.152,73.337 42.152,73.452 42.39,73.69 CN1.B5@42.39,74.298
  Bottom Layer w0.3: v1@41.16,70.29 v1(41.16,70.303) 41.16,72.317 v1@42.168,73.325
  other v1: 42.162,73.352
NetCN4_9: CN4.9 R22.2 | length 8.5
  Top Layer w0.152: CN4.9@2.672,62.737 2.682,62.727 v1(4.517,62.727) ; v1(8.828,64.768) 9.175,64.768 9.42,65.013 R22.2@10.236,65.013
  Bottom Layer w0.152: v1(4.517,62.727) 6.558,64.768 v1(8.828,64.768)
NetCN5_8: CN5.8 CN10.7 SB4.1 | length 11.2
  Top Layer w0.4: SB4.1@53.847,43.24 54.416,42.672 CN5.8@59.131,42.672 60.905,42.672 62.43,41.148 CN10.7@64.211,41.148
NetCN6_1: CN6.1 R33.2 | length 4
  Top Layer w0.5: R33.2@11.083,41.485 11.833,41.485 v2(11.853,41.465)
  Bottom Layer w0.5: CN6.1@10.871,38.608 10.871,40.484 v2(11.853,41.465)
NetCN7_13: CN7.13 SB9.2 | length 26.3
  Top Layer w0.152: CN7.13@3.251,33.528 4.496,32.283 v1(13.647,32.284) ; v1(13.647,40.42) 18.752,40.42 19.566,41.234 SB9.2@20.558,41.234
  Bottom Layer w0.152: v1@13.641,32.29 v1(13.647,32.284) v1(13.647,32.284) v1(13.647,40.42)
NetCN7_15: CN7.15 SB10.2 | length 27.2
  Top Layer w0.152: CN7.15@3.251,30.988 4.503,29.736 v1@13.191,29.736 ; v1(13.192,29.735) v1@13.191,29.736 ; v1(13.193,38.573) 19.458,38.573 SB10.2@20.558,39.672 ; v1@13.283,29.736 v1@13.191,29.736
  Bottom Layer w0.152: v1(13.192,29.735) v1(13.193,38.573)
NetCN7_25: CN7.25 SB14.2 | length 26.2
  Top Layer w0.152: CN7.25@3.251,18.288 4.477,17.063 7.918,17.063 8.625,17.77 v1(16.618,17.77) ; v1(17.073,24.182) 21.852,24.182 22.283,24.613 SB14.2@22.29,24.605
  Bottom Layer w0.152: v1(16.618,17.77) 16.614,17.773 16.614,22.857 17.073,23.316 v1(17.073,24.182)
NetCN7_27: CN7.27 SB17.2 | length 28.3
  Top Layer w0.152: CN7.27@3.251,15.748 4.537,14.463 15.748,14.463 18.315,17.03 SB17.2@29.983,17.03
NetCN7_29: CN7.29 SB19.2 | length 39.1
  Top Layer w0.152: CN7.29@3.251,13.208 4.477,11.983 13.99,11.983 18.275,16.268 35.157,16.268 35.776,15.649 38.549,15.649 38.933,16.033 SB19.2@38.933,16.712
NetCN7_31: CN7.31 SB18.2 | length 47
  Top Layer w0.152: CN7.31@3.251,10.668 4.507,9.413 12.37,9.413 18.921,15.963 35.027,15.963 35.652,15.338 45.12,15.338 45.807,16.025 SB18.2@45.807,16.718
NetCN13_A5: CN13.A5 R45.1 | length 2.8
  Top Layer w0.22: R45.1@16.669,7.264 17.304,6.629 18.339,6.629 18.621,6.347 CN13.A5@18.621,5.868
NetCN13_B5: CN13.B5 R47.1 | length 6.6
  Top Layer w0.3: CN13.B5@19.871,4.168 19.871,5.012 v1(19.914,5.055) ; v1(24.663,5.918) R47.1@25.248,5.918
  Bottom Layer w0.3: v1(19.914,5.055) 20.777,5.918 v1(24.663,5.918)
NetJP9_1: JP9.1 R46.2 | length 2.1
  Top Layer w0.152: R46.2@33.368,8.001 JP9.1@35.425,8.001
NetLD1_1: LD1.1 R15.1 | length 3.7
  Top Layer w0.2: LD1.1@51.78,65.808 R15.1@51.78,69.533
NetLD1_2: LD1.2 T2.3 | length 10.5
  Top Layer w0.2: T2.3@47.495,57.76 47.128,58.127 47.128,60.555 47.85,61.277 50.405,61.277 51.125,61.997 51.125,64.053 LD1.2@51.78,64.708
NetLD2_1: LD2.1 R16.1 | length 3.7
  Top Layer w0.2: LD2.1@54.305,65.808 R16.1@54.305,69.533
NetLD3_1: LD3.1 R31.2 | length 1.1
  Top Layer w0.2: LD3.1@66.03,55.748 R31.2@67.178,55.748
NetLD4_1: LD4.1 R12.1 | length 1.5
  Top Layer w0.152: R12.1@60.147,73.433 LD4.1@60.147,74.941
  Top Layer w0.2: LD4.1@60.13,74.958 LD4.1@60.147,74.941
NetLD4_2: LD4.2 R11.2 | length 1.5
  Top Layer w0.152: R11.2@58.623,73.433 LD4.2@58.623,74.951
  Top Layer w0.2: LD4.2@58.623,74.951 LD4.2@58.63,74.958
NetLD5_1: LD5.1 R10.1 | length 2.6
  Top Layer w0.2: R10.1@56.083,73.475 LD5.1@56.083,76.056
NetLD5_2: LD5.2 R2.1 U1.3 | length 4.4
  Top Layer w0.2: U1.3@53.043,75.838 R2.1@53.043,77.156 LD5.2@56.083,77.156
NetR3_2: R3.2 R6.1 R7.1 T1.1 | length 3.6
  Top Layer w0.152: T1.1@34.077,75.219 33.934,75.077 R6.1@33.934,73.721 R7.1@34.959,73.721 R3.2@35.983,73.721
NetR4_2: R4.2 T1.2 | length 1.9
  Top Layer w0.152: T1.2@35.977,75.219 35.977,75.072 37.008,74.041 R4.2@37.008,73.721
NetR8_2: R8.2 U3.44 | length 2
  Top Layer w0.152: R8.2@30.778,72.82 31.178,72.421 U3.44@31.178,70.982
NetR13_1: R13.1 U3.2 | length 4.3
  Top Layer w0.152: R13.1@25.371,71.403 26.362,71.403 26.812,70.953 26.812,69.19 27.02,68.982 U3.2@27.678,68.982
NetR18_1: R18.1 U3.3 | length 3.7
  Top Layer w0.152: R18.1@25.371,70.293 26.242,70.293 26.508,70.027 26.508,68.959 26.985,68.482 U3.3@27.678,68.482
NetR20_1: R20.1 R21.2 U6.C1 | length 1.8
  Top Layer w0.152: U6.C1@47.901,66.218 47.901,67.041 R20.1@47.754,67.188 R21.2@48.517,67.188
NetR23_1: R23.1 U3.29 | length 2.7
  Top Layer w0.152: U3.29@36.178,65.982 37.19,65.982 38.314,64.858 R23.1@38.377,64.858
NetR28_2: R28.2 R30.1 U9.5 | length 2.5
  Top Layer w0.3: U9.5@55.336,59.09 55.41,59.015 56.248,59.015 R28.2@56.64,58.623 R30.1@56.64,57.585
NetR29_1: R29.1 SB1.1 T2.1 | length 3.6
  Top Layer w0.152: 42.536,59.06 43.49,59.06 43.855,58.695 R29.1@43.855,58.21 44.795,58.21 T2.1@45.295,58.71
NetR43_2: R43.2 R44.1 U17.C1 | length 2.6
  Top Layer w0.152: U17.C1@24.575,9.366 24.575,9.72 25.298,10.443 R44.1@25.298,10.492 R43.2@25.298,11.533 R43.2@25.298,11.633
NetTP1_1: TP1.1 U6.B1 | length 1.6
  Top Layer w0.152: U6.B1@47.901,65.818 49.295,65.818 TP1.1@49.427,65.686
NetTP3_1: TP3.1 U9.3 | length 1.7
  Top Layer w0.25: TP3.1@51.035,58.14 U9.3@52.736,58.14
NetTP5_1: TP5.1 U17.B1 | length 3.2
  Top Layer w0.15: U17.B1@24.975,9.366 24.975,9.655 25.234,9.914 25.767,9.914 25.865,10.012 25.865,10.458 26.16,10.753 TP5.1@26.982,10.753 ; TP5.1@26.855,10.88 TP5.1@26.982,11.007
NRST: B2.3 B2.4 C36.2 CN4.12 CN6.3 CN7.14 JP7.1 U8.5 U12.1 U14.12 | length 134.7
  Top Layer w0.152: CN7.14@5.791,33.528 CN6.3@10.871,33.528 11.642,32.758 v1(15.015,32.758) ; CN4.12@6.736,61.467 9.293,61.467 10.232,60.528 U8.5@10.232,60.504 ; U8.5@10.232,60.115 U8.5@10.232,60.504 ; v1(15.012,42.922) 15.051,42.961 28.673,42.961 30.855,45.143 41.965,45.143 42.202,44.906 v1(46.08,44.905) v1(46.08,44.905) ; JP7.1@15.316,61.468 11.195,61.468 U8.5@10.232,60.504 ; U14.12@37.749,25.533 37.749,24.576 38.92,23.405 40.558,23.405 45.575,18.388 C36.2@45.575,18.293 45.562,18.28 v1(45.562,17.76) ; B2.3@40.456,49.308 B2.4@46.056,49.308 U12.1@48.303,49.308 ; v1(47.487,48.15) 47.675,48.15 47.682,48.158 47.685,48.155 48.305,48.775 U12.1@48.305,49.31
  Bottom Layer w0.152: v1@11.903,61.473 11.763,61.333 11.763,56.272 13.474,54.561 13.474,46.791 15.012,45.253 v1(15.012,42.922) ; v1@15.011,32.758 v1@15.011,42.885 ; v1(45.562,17.76) 45.562,18.41 46.521,19.368 46.521,28.457 46.18,28.798 46.18,44.805 v1(46.08,44.905) 46.08,47.08 47.15,48.15 v1(47.487,48.15)
  other v1: 11.813,61.473
PA0: CN7.28 CN8.1 U14.17 | length 46.7
  Top Layer w0.152: CN7.28@5.791,15.748 CN8.1@10.871,15.748 ; v1@12.5,26.642 28.487,26.642 28.755,26.91 31.213,26.91 31.603,27.3 39.19,27.3 39.415,27.075 40.619,27.075 41.227,27.683 U14.17@41.899,27.683
  Bottom Layer w0.152: CN8.1@10.871,15.748 12.5,17.377 v1(12.5,26.64)
PA1: CN7.30 CN8.2 U14.18 | length 49.6
  Top Layer w0.152: CN7.30@5.791,13.208 CN8.2@10.871,13.208 ; v1(12.962,27.15) 28.385,27.15 28.495,27.26 31.133,27.26 31.477,27.605 39.355,27.605 39.581,27.379 40.324,27.379 40.665,27.72 40.665,27.97 40.878,28.183 U14.18@41.899,28.183
  Bottom Layer w0.152: CN8.2@10.871,13.208 12.962,15.299 v1(12.962,27.15)
PA2: CN4.14 CN10.18 R27.2 U8.1 U14.19 | length 96.5
  Top Layer w0.152: CN4.14@6.736,60.197 8.838,60.197 U8.1@10.232,58.803 ; U8.1@10.232,58.415 U8.1@10.232,58.803 ; v1(19.384,57.674) 14.058,57.674 12.48,59.253 10.596,59.253 10.232,58.888 U8.1@10.232,58.803 ; v1(21.828,59.688) 21.975,59.688 29.025,59.688 29.008,59.67 v1(29.008,59.207) ; v1(32.228,59.618) 40.542,59.618 41.13,59.03 v1(41.13,58.975) ; U14.19@41.899,28.683 v1(44.565,28.683) 57.045,28.683 57.495,28.232 58.279,28.232 58.73,28.683 60.782,28.683 62.28,27.185 65.488,27.185 CN10.18@66.751,28.448
  Bottom Layer w0.152: v1(19.384,57.674) 19.814,57.674 v1(21.828,59.688) ; v1(29.008,59.207) 29.012,59.207 29.423,59.618 v1(32.228,59.618) ; v1(41.13,58.975) 41.13,57.44 44.513,54.057 44.513,36.167 44.957,35.723 44.957,31.024 44.513,30.579 44.513,28.736 v1(44.565,28.683)
PA3: CN4.13 CN10.6 R26.2 U8.3 U14.20 | length 105.6
  Top Layer w0.152: CN4.13@2.672,60.197 3.726,60.197 4.54,59.382 7.46,59.382 8.287,58.555 8.287,57.285 8.582,56.99 11.205,56.99 11.532,57.317 U8.3@11.532,58.415 12.775,58.415 14.038,57.152 v1(18.792,57.152) ; v1(23.384,60.603) 23.779,60.998 R26.2@24.475,60.998 24.475,60.848 24.948,60.374 27.07,60.374 v1(27.326,60.629) ; v1(32.213,60.347) 32.998,60.347 33.423,59.922 40.94,59.922 41.658,59.205 v1(41.658,58.46) ; U14.20@41.899,29.183 v1(44.993,29.182) ; v1(44.966,41.239) 44.967,41.238 55.246,41.238 55.388,41.38 60.9,41.38 62.375,39.905 64.873,39.905 65.497,40.529 65.497,42.434 CN10.6@66.751,43.688
  Bottom Layer w0.152: v1(18.792,57.152) 19.934,57.152 v1(23.384,60.603) ; v1(27.326,60.629) 27.336,60.629 27.942,60.023 31.888,60.023 v1(32.213,60.347) ; 41.657,57.618 44.967,54.308 v1@44.967,41.24 ; 41.658,57.619 v1(41.658,58.46) ; v1@44.967,41.239 44.967,36.25 45.262,35.956 45.262,30.898 44.967,30.603 44.967,29.208 v1(44.993,29.182)
PA4: CN7.32 CN8.3 U14.21 | length 56.7
  Top Layer w0.152: CN7.32@5.791,10.668 CN8.3@10.871,10.668 ; v1(13.417,28.315) v1(28.397,28.315) ; v1(31.68,31.942) 39.893,31.942 40.752,31.083 40.752,29.863 40.932,29.683 U14.21@41.899,29.683
  Bottom Layer w0.152: CN8.3@10.871,10.668 13.417,13.214 v1(13.417,28.315) ; v1(28.397,28.315) 30.252,28.315 31.68,29.743 v1(31.68,31.942)
PA5: CN5.6 CN10.11 SB1.2 U14.22 | length 53
  Top Layer w0.152: U14.22@41.899,30.183 44.849,30.183 v1(45.421,30.182) ; 42.536,57.96 42.536,57.044 43.312,56.267 v1(44.162,56.267) ; v1@45.421,36.528 49.025,36.528 49.37,36.872 57.08,36.872 57.8,37.592 CN5.6@59.131,37.592 60.511,37.592 62.035,36.068 CN10.11@64.211,36.068
  Bottom Layer w0.152: v1(44.162,56.267) 45.322,55.108 45.322,44.142 45.421,44.044 v1(45.421,36.528) 45.571,36.378 45.571,30.75 45.421,30.6 v1(45.421,30.182)
PA6: CN5.5 CN10.13 U14.23 | length 29.6
  Top Layer w0.152: U14.23@41.899,30.683 54.688,30.683 55.333,31.328 60.959,31.328 60.964,31.323 v1(60.964,31.309) ; CN5.5@59.131,35.052 60.591,35.052 62.115,33.528 CN10.13@64.211,33.528
  Bottom Layer w0.152: CN5.5@59.131,35.052 60.964,33.219 v1(60.964,31.309) v1@60.967,31.313
PA7: CN5.4 CN10.15 U14.24 | length 23.5
  Top Layer w0.152: U14.24@41.899,31.183 54.641,31.183 55.194,31.737 58.356,31.737 CN5.4@59.131,32.512 61.041,32.512 62.565,30.988 CN10.15@64.211,30.988
PA8: CN9.8 CN10.23 U14.36 | length 46.3
  Top Layer w0.152: U14.36@38.249,37.333 38.249,38.557 40.44,40.748 42.315,40.748 43.602,39.46 50.944,39.46 ; 50.945,39.461 51.614,39.461 52.107,38.968 v1(56.353,38.968) v1@56.366,38.968 ; CN9.8@59.131,20.828 CN10.23@64.211,20.828
  Bottom Layer w0.152: v1(56.353,38.968) 56.353,32.747 57.265,31.835 57.265,21.137 57.575,20.828 CN9.8@59.131,20.828
PA9: CN5.1 CN10.21 U14.37 | length 46.2
  Top Layer w0.152: U14.37@37.749,37.333 37.749,38.566 41.026,41.843 42.938,41.843 42.955,41.843 53.365,41.843 53.514,41.694 v1(54.321,41.694) ; v1(55.143,24.75) 55.285,24.892 CN5.1@59.131,24.892 60.918,24.892 62.442,23.368 CN10.21@64.211,23.368
  Bottom Layer w0.152: v1@54.232,41.602 54.232,38.093 54.52,37.805 54.52,31.283 55.143,30.66 v1@55.143,24.85 ; v1(55.143,24.75) v1@55.143,24.85 ; v1@55.162,24.87 v1@55.143,24.85
PA10: CN9.3 CN10.33 U14.42 | length 68.4
  Top Layer w0.152: U14.42@35.249,37.333 35.245,40.147 34.763,40.63 34.763,43.918 35.074,44.229 41.126,44.229 41.822,43.533 v1(52.873,43.533) ; CN9.3@59.131,8.128 CN10.33@64.211,8.128
  Bottom Layer w0.152: v1(52.873,43.533) 53.249,43.156 53.249,31.372 54.383,30.237 54.383,12.876 CN9.3@59.131,8.128
PA11: CN10.14 SB7.1 | length 45.7
  Top Layer w0.152: SB7.1@34.01,42.953 34.01,44.125 34.419,44.534 41.361,44.534 41.908,43.987 v1(51,43.987) ; v1(50.675,34.458) 58.075,34.458 58.69,33.843 60.695,33.843 62.25,32.287 65.511,32.287 CN10.14@66.751,33.528
  Bottom Layer w0.152: v1(50.675,34.458) 50.675,43.662 v1(51,43.987)
PA12: CN10.12 SB6.1 | length 45.7
  Top Layer w0.152: SB6.1@32.613,42.953 32.613,44.103 33.348,44.838 41.649,44.838 42.036,44.452 v1@50.546,44.452 ; v1(50.22,36.417) 57.335,36.417 57.448,36.531 58.561,36.531 58.83,36.263 60.618,36.263 62.113,34.767 65.451,34.767 CN10.12@66.751,36.068 ; v1(50.546,44.453) v1@50.553,44.46
  Bottom Layer w0.152: v1(50.22,36.417) 50.22,44.108 v1@50.565,44.453 ; v1(50.546,44.453) v1@50.565,44.453 ; v1@50.63,44.518 v1@50.565,44.453
PA13: CN4.4 JP2.1 SB9.1 U4.5 U14.45 | length 66.5
  Top Layer w0.152: CN4.4@6.736,66.547 8.814,66.547 9.088,66.82 9.088,68.502 9.438,68.853 U4.5@10.232,68.853 10.232,71.122 10.738,71.628 JP2.1@15.316,71.628 ; v1(17.37,41.868) 17.881,41.868 18.046,42.032 21.488,42.032 21.658,41.862 SB9.1@21.658,41.234 22.435,42.01 30.053,42.01 33.749,38.313 U14.45@33.749,37.333
  Bottom Layer w0.152: JP2.1@15.316,71.628 12.704,69.016 12.704,56.656 14.393,54.967 14.393,53.339 14.392,53.338 14.392,49.293 15.395,48.29 16.7,48.29 17.37,47.62 v1(17.37,41.868)
PA14: CN4.6 JP4.1 R22.1 SB3.1 SB10.1 U4.1 U14.46 | length 59.7
  Top Layer w0.152: CN4.6@6.736,65.277 8.499,65.277 9.159,65.936 10.232,65.936 U4.1@10.232,67.153 10.232,67.626 10.603,67.997 13.867,67.997 JP4.1@15.316,66.548 ; v1(17.94,48.87) 18.665,48.145 SB3.1@18.988,48.145 ; v1(19.45,40.458) 21.482,40.458 21.657,40.283 SB10.1@21.657,39.672 21.858,39.672 22.991,40.806 30.782,40.806 33.249,38.338 U14.46@33.249,37.333
  Bottom Layer w0.152: JP4.1@15.316,66.548 13.553,64.785 13.553,62.52 13.62,62.453 13.62,57.217 15.308,55.529 15.308,50.108 16.198,49.218 17.587,49.218 18.328,48.477 18.328,41.579 v1(19.45,40.458)
PA15: CN5.3 CN10.17 U14.47 | length 44.2
  Top Layer w0.152: U14.47@32.749,37.333 32.749,36.336 32.898,36.187 39.94,36.187 40.18,36.428 40.18,38.553 40.922,39.295 41.916,39.295 43.605,37.606 52.979,37.606 53.888,38.515 v1(54.685,38.515) ; v1(55.69,30.875) 58.228,30.875 CN5.3@59.131,29.972 60.611,29.972 62.135,28.448 CN10.17@64.211,28.448
  Bottom Layer w0.152: v1(54.685,38.515) 54.685,38.07 54.824,37.931 54.824,31.741 v1(55.69,30.875)
PB0: CN7.34 CN8.4 U14.27 | length 59.2
  Top Layer w0.152: CN7.34@5.791,8.128 CN8.4@10.871,8.128 ; v1@13.882,29.742 v1(27.945,29.742) v1@27.942,29.74 ; v1(32.243,33.35) 40.205,33.35 40.872,32.683 U14.27@41.899,32.683
  Bottom Layer w0.152: CN8.4@10.871,8.128 13.882,11.139 v1(13.882,29.747) ; v1(27.945,29.742) 27.95,29.737 29.912,29.737 30.56,30.385 30.56,32.927 30.983,33.35 v1(32.243,33.35)
PB1: CN10.24 U14.28 | length 38.2
  Top Layer w0.152: U14.28@41.899,33.183 v1(50.675,33.183) ; v1(52.107,19.55) 65.473,19.55 CN10.24@66.751,20.828
  Bottom Layer w0.152: v1(50.675,33.183) 50.675,31.17 52.107,29.738 v1(52.107,19.55) v1@52.129,19.527
PB2: CN7.35 U14.29 | length 66.4
  Top Layer w0.152: CN7.35@3.251,5.588 4.547,4.293 v1(12.093,4.293) ; v1(14.798,30.276) 28.359,30.276 v1(28.377,30.295) ; v1(31.68,33.803) 33.927,33.803 34.048,33.683 U14.29@41.899,33.683
  Bottom Layer w0.152: v1(12.093,4.293) 12.093,6.013 14.798,8.718 v1(14.798,30.276) ; v1(28.377,30.295) 29.661,30.295 30.099,30.733 30.099,33.046 30.856,33.803 v1(31.68,33.803)
PB3: CN4.8 CN5.2 CN10.19 JP6.1 U4.3 U14.57 | length 102.9
  Top Layer w0.152: CN4.8@6.736,64.007 10.462,64.007 11.678,65.223 11.678,67.006 U4.3@11.532,67.153 13.5,67.153 14.028,66.625 14.028,65.297 JP6.1@15.316,64.008 12.549,64.008 v1(11.839,63.299) ; v1@14.082,31.19 v1(14.101,31.19) 15.518,31.19 15.519,31.191 15.965,31.191 15.973,31.183 U14.57@30.099,31.183 38.467,31.183 v1(40.057,29.593) ; v1(43.198,28.228) 57.07,28.228 57.866,27.432 CN5.2@59.131,27.432 60.813,27.432 62.337,25.908 CN10.19@64.211,25.908
  Bottom Layer w0.152: v1(11.839,63.299) 11.871,63.299 11.322,62.75 11.322,56.21 13.17,54.363 13.17,46.563 14.101,45.632 v1@14.101,31.191 ; v1(40.057,29.593) 41.832,29.593 v1(43.198,28.228)
PB4: CN9.6 CN10.27 U14.58 | length 45.3
  Top Layer w0.152: U14.58@30.099,30.683 30.107,30.691 31.534,30.691 31.693,30.85 38.159,30.85 40.006,29.002 v1(40.492,29.002) ; v1(43.298,27.423) 44.078,26.642 v1@56.505,26.642 ; CN9.6@59.131,15.748 CN10.27@64.211,15.748
  Bottom Layer w0.152: v1(40.492,29.002) 41.718,29.002 v1(43.298,27.423) ; v1(56.506,26.642) 56.506,18.374 CN9.6@59.131,15.748
PB5: CN9.5 CN10.29 U14.59 | length 48.5
  Top Layer w0.152: U14.59@30.099,30.183 31.457,30.183 31.819,30.546 37.962,30.546 v1(39.962,28.545) ; v1(42.68,27.073) 43.735,26.017 v1(56.052,26.017) ; CN9.5@59.131,13.208 CN10.29@64.211,13.208
  Bottom Layer w0.152: v1(39.962,28.545) 41.207,28.545 v1(42.68,27.073) ; v1(56.052,26.017) 56.052,13.928 56.772,13.208 CN9.5@59.131,13.208
PB6: CN9.2 CN10.35 U14.60 | length 52.9
  Top Layer w0.152: U14.60@30.099,29.683 31.387,29.683 31.945,30.241 37.489,30.241 39.822,27.908 v1(40.105,27.908) ; v1@43.562,24.817 v1(51.19,24.817) ; v1(56.895,5.589) CN9.2@59.131,5.588 CN10.35@64.211,5.588
  Bottom Layer w0.152: v1(40.105,27.908) 41.102,27.908 43.527,25.482 v1(43.527,24.817) ; v1(51.19,24.817) 51.341,24.667 51.341,18.925 51.786,18.48 51.786,12.482 56.319,7.948 56.319,6.165 v1(56.895,5.589) v1@56.984,5.589
PB7: CN9.1 CN10.37 U14.61 | length 54.9
  Top Layer w0.152: U14.61@30.099,29.183 31.318,29.183 32.071,29.937 37.064,29.937 38.847,28.154 v1(38.847,28.112) ; v1(43.035,24.202) v1(50.885,24.202) ; v1(57.338,3.049) 57.339,3.048 CN9.1@59.131,3.048 CN10.37@64.211,3.048
  Bottom Layer w0.152: v1(38.847,28.112) 39.506,27.454 40.973,27.454 43.035,25.393 v1(43.035,24.202) ; v1(50.885,24.202) 50.885,18.95 51.481,18.354 51.481,12.211 52.825,10.868 55.968,7.725 55.968,4.419 v1(57.338,3.049) v1@57.354,3.065
PB8: CN5.10 CN10.3 U14.62 | length 51.8
  Top Layer w0.152: U14.62@30.099,28.683 31.248,28.683 32.198,29.633 36.727,29.633 v1(37.128,29.232) ; v1(43.302,32.7) 57.258,32.7 v1(57.268,32.71) ; v1(57.268,47.752) CN5.10@59.131,47.752 61.148,47.752 62.672,46.228 CN10.3@64.211,46.228
  Bottom Layer w0.152: v1(37.128,29.232) 40.595,32.7 v1(43.302,32.7) ; v1(57.268,32.71) v1(57.268,47.752)
PB9: CN5.9 CN10.5 U14.63 | length 50.2
  Top Layer w0.152: U14.63@30.099,28.183 31.376,28.183 32.521,29.328 36.371,29.328 37.087,28.613 v1(37.513,28.613) ; v1@43.647,32.243 v1@43.727,32.243 ; v1(43.727,32.19) v1(55.732,32.19) ; v1(56.358,45.211) 56.359,45.212 CN5.9@59.131,45.212 60.803,45.212 62.327,43.688 CN10.5@64.211,43.688
  Bottom Layer w0.152: v1(37.513,28.613) 37.581,28.68 37.581,29.125 40.646,32.19 v1(43.727,32.19) ; v1(55.732,32.19) 55.445,32.478 55.445,38.997 56.358,39.91 v1(56.358,45.211)
PB10: CN10.34 U14.30 | length 48.4
  Top Layer w0.152: U14.30@41.899,34.183 43.002,34.183 43.517,33.667 v1(50.183,33.667) ; v1@56.896,6.873 65.496,6.873 CN10.34@66.751,8.128
  Bottom Layer w0.152: v1(50.183,33.667) 50.183,31.077 51.645,29.615 51.645,19.27 52.09,18.825 52.09,12.652 56.895,7.847 v1(56.895,6.873)
PB11: CN7.37 U14.31 | length 69.4
  Top Layer w0.152: CN7.37@3.251,3.048 4.589,1.71 v1(11.995,1.71) ; v1@15.717,30.73 v1(27.783,30.73) ; v1(32.243,34.258) 33.543,34.258 34.548,35.262 40.267,35.262 40.847,34.683 U14.31@41.899,34.683
  Bottom Layer w0.152: v1(11.995,1.71) 11.995,2.178 12.979,3.162 12.979,6.038 15.707,8.766 v1@15.707,30.727 ; v1(27.783,30.73) 27.802,30.748 29.256,30.748 29.717,31.21 29.717,33.318 30.658,34.258 v1(32.243,34.258)
  other v1: 15.707,30.738
PB12: CN10.16 U14.32 | length 29
  Top Layer w0.152: U14.32@41.899,35.183 42.932,35.183 43.994,34.121 50.37,34.121 50.855,33.637 58.198,33.637 v1(58.225,33.61) ; v1(60.497,30.775) 61.527,29.745 65.508,29.745 CN10.16@66.751,30.988
  Bottom Layer w0.152: v1(58.225,33.61) 58.28,33.665 59.865,33.665 60.497,33.033 v1(60.497,30.775)
PB13: CN10.30 U14.33 | length 55.1
  Top Layer w0.152: U14.33@39.749,37.333 39.749,38.704 40.655,39.61 42.032,39.61 43.579,38.062 v1(52.038,38.062) ; v1(53.604,11.924) 53.607,11.927 65.471,11.927 CN10.30@66.751,13.208
  Bottom Layer w0.152: v1(52.038,38.062) 52.038,31.22 53.47,29.788 53.47,12.051 53.6,11.921 v1(53.604,11.924)
PB14: CN10.28 U14.34 | length 53.7
  Top Layer w0.152: U14.34@39.249,37.333 39.249,38.696 40.496,39.943 42.13,39.943 43.542,38.53 v1(51.583,38.53) ; v1(53.016,14.479) v1(53.016,14.479) 65.483,14.48 CN10.28@66.751,15.748
  Bottom Layer w0.152: v1(51.583,38.53) 51.583,31.245 53.016,29.811 v1(53.016,14.479)
PB15: CN10.26 U14.35 | length 52.4
  Top Layer w0.152: U14.35@38.749,37.333 38.749,38.626 40.435,40.313 42.19,40.313 43.495,39.007 ; 43.496,39.007 v1(51.133,39.007) ; v1@52.562,17.005 65.468,17.005 CN10.26@66.751,18.288
  Bottom Layer w0.152: v1(51.133,39.007) 51.129,39.004 51.129,31.188 52.562,29.756 v1(52.562,17.006) v1@52.687,17.006
PC0: CN10.22 R39.2 R40.1 U14.13 | length 31.5
  Top Layer w0.152: U14.13@38.249,25.533 38.249,24.556 39.091,23.714 40.679,23.714 42.863,21.53 51.09,21.53 55.945,21.53 56.557,22.143 65.526,22.143 CN10.22@66.751,23.368
PC1: CN10.4 U14.14 | length 54.6
  Top Layer w0.152: U14.14@38.749,25.533 38.749,24.563 39.294,24.018 40.805,24.018 41.532,23.292 v1(55.598,23.292) ; v1(55.903,43.974) 55.904,43.973 60.978,43.973 62.553,42.397 65.025,42.397 65.427,42.8 65.427,44.904 CN10.4@66.751,46.228
  Bottom Layer w0.152: v1@55.595,23.292 55.596,23.292 55.596,24.938 55.595,24.939 55.595,26.538 56.515,27.458 56.515,30.743 55.14,32.117 55.14,39.123 55.909,39.892 55.909,43.98 v1(55.903,43.974)
PC2: CN7.21 U14.15 | length 41.4
  Top Layer w0.152: CN7.21@3.251,23.368 4.498,24.615 12.458,24.615 13.313,25.47 24.143,25.47 25.972,23.641 30.448,23.641 31.538,24.731 31.538,26.576 31.958,26.996 38.984,26.996 39.249,26.731 U14.15@39.249,25.533
PC3: CN10.1 U14.16 | length 51.2
  Top Layer w0.152: U14.16@39.749,25.533 39.749,24.556 39.983,24.322 40.931,24.322 41.509,23.745 v1(57.72,23.745) v1@57.723,23.745 ; v1(57.723,49.04) 61.015,49.04 61.287,48.768 CN10.1@64.211,48.768
  Bottom Layer w0.152: v1@57.723,23.745 v1(57.723,49.04)
PC4: CN7.36 CN8.5 U14.25 | length 60.4
  Top Layer w0.152: CN7.36@5.791,5.588 CN8.5@10.871,5.588 ; v1@14.345,28.798 v1(27.96,28.798) ; v1(32.243,32.4) 39.865,32.4 40.582,31.683 U14.25@41.899,31.683
  Bottom Layer w0.152: CN8.5@10.871,5.588 14.345,9.062 v1(14.345,28.8) ; v1(27.96,28.798) 30.228,28.798 31.21,29.78 31.21,32.114 31.496,32.4 v1(32.243,32.4)
PC5: CN7.38 CN8.6 U14.26 | length 63.8
  Top Layer w0.152: CN7.38@5.791,3.048 CN8.6@10.871,3.048 ; v1(15.254,29.275) 15.251,29.278 v1(28.4,29.278) ; v1(31.68,32.897) 40.038,32.897 40.752,32.183 U14.26@41.899,32.183
  Bottom Layer w0.152: CN8.6@10.871,3.048 12.36,3.048 12.675,3.363 12.675,6.165 15.254,8.743 v1(15.254,29.275) ; v1(28.4,29.278) 30.013,29.278 30.886,30.15 30.886,32.536 31.247,32.897 v1(31.68,32.897)
PC6: CN7.17 U14.38 | length 46.9
  Top Layer w0.152: CN7.17@3.251,28.448 4.514,27.185 v1(11.91,27.185) ; v1(12.283,37.765) 12.448,37.599 27.647,37.599 v1(28.112,38.065) ; U14.38@37.249,37.333 v1@37.249,38.535
  Bottom Layer w0.152: v1(11.91,27.185) 12.275,27.55 v1@12.275,37.765 ; v1(12.283,37.765) 12.283,38.052 ; v1(28.112,38.065) 35.806,38.065 36.386,38.645 v1(37.257,38.645)
PC7: CN9.4 CN10.31 U14.39 | length 59.9
  Top Layer w0.152: U14.39@36.749,37.333 36.749,38.879 37.439,39.569 38.321,39.569 40.9,42.148 v1(53.702,42.148) ; CN9.4@59.131,10.668 CN10.31@64.211,10.668
  Bottom Layer w0.152: v1(53.702,42.148) 53.702,38.622 53.602,38.523 53.602,31.448 54.687,30.363 54.687,13.053 57.072,10.668 CN9.4@59.131,10.668
PC8: CN9.7 CN10.25 U14.48 | length 55.2
  Top Layer w0.152: U14.48@32.249,37.333 32.249,36.193 32.563,35.88 40.063,35.88 40.484,36.302 40.484,38.426 41.033,38.975 41.74,38.975 43.413,37.302 53.224,37.302 53.828,37.906 v1(55.898,37.906) ; CN9.7@59.131,18.288 CN10.25@64.211,18.288
  Bottom Layer w0.152: v1@55.899,37.906 55.899,32.678 56.961,31.617 56.961,19.172 57.845,18.288 CN9.7@59.131,18.288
